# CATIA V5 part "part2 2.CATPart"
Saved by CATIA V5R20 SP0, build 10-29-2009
Part number: UFO底座2
Bounding box of the stored display mesh (mm): x -45 to 45, y -45 to 44.964, z -60 to 0
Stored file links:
  C:\Users\16057\Documents\180511420 创意设计\part2 2.CATPart
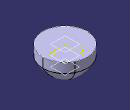
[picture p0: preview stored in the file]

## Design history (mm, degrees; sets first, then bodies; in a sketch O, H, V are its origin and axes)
Body1 (main body)
  Plane1: type Offset, RefPlane xy-plane, Offset 20, reversed
  Plane2: type Offset, RefPlane Plane1, Offset 20, reversed
  Sketch1 on Plane2, origin (0, 0, -40), H (1, 0, 0), V (0, 1, 0)
    circle A1 centre (0, 0) radius 30
    radius A1 = 30
  Sketch2 on Plane1, origin (0, 0, -20), H (1, 0, 0), V (0, 1, 0)
    circle A1 centre (0, 0) radius 45
    radius A1 = 45
  Sketch3 on xy-plane, origin (0, 0, 0), H (1, 0, 0), V (0, 1, 0)
    circle A1 centre (0, 0) radius 45
    radius A1 = 45
  Plane3: type Offset, RefPlane Plane2, Offset 20, reversed
  Sketch4 on Plane3, origin (0, 0, -60), H (1, 0, 0), V (0, 1, 0)
    circle A1 centre (0, 0) radius 0.05
    radius A1 = 0.05
  Loft1: solid, Sections (Sketch4; Sketch1; Sketch2)
  Pad1: profile face of Loft1, direction along Plane1, length 20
